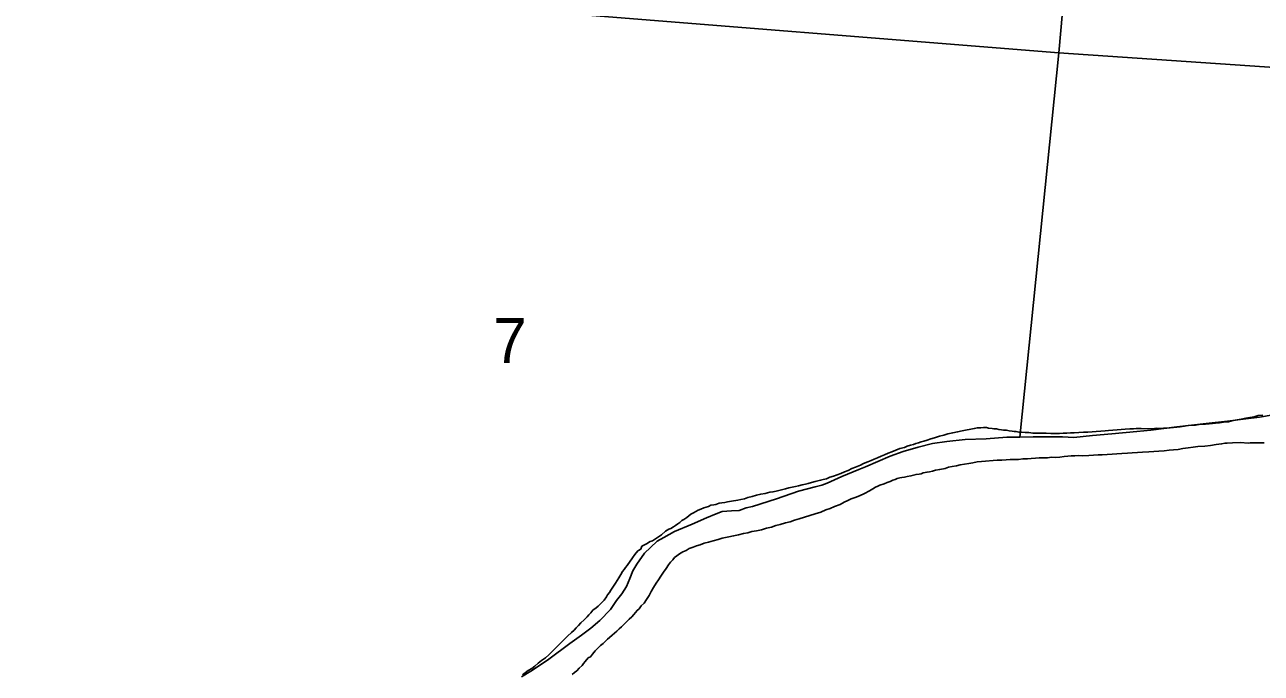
# Model space of a CAD drawing. Extents: x -1.4 to 35.4, y 0 to 22.
# Drawn here: x 20.952 to 22.111, y 16.062 to 16.67 of the extents above; entities that cross this region are included whole.
import ezdxf

# ---------------------------------------------------------------- set-up
doc = ezdxf.new("R2010")
doc.units = 0
for name, color, linetype in [('GM_X_Major_River', 7, 'Continuous'), ('GM_X_Section', 7, 'Continuous'), ('GM_X_Section_Text', 7, 'Continuous')]:
    doc.layers.add(name, color=color, linetype=linetype)

msp = doc.modelspace()

# ---------------------------------------------------------------- linework, layer by layer
at = {"layer": 'GM_X_Major_River'}
for points in [[(22.0755, 16.2976), (22.0804, 16.2979), (22.0846, 16.299), (22.0884, 16.2997), (22.0922, 16.3004), (22.0964, 16.3011), (22.1002, 16.3018), (22.1044, 16.3025), (22.1082, 16.3036), (22.1124, 16.3039)], [(21.7271, 16.254), (21.7306, 16.2554), (21.7352, 16.2573), (21.7382, 16.2587), (21.742, 16.2602), (21.7451, 16.2617), (21.7481, 16.2628), (21.7512, 16.2642), (21.7546, 16.2657), (21.7577, 16.2668), (21.7611, 16.2683), (21.7645, 16.2698), (21.7684, 16.2712), (21.7722, 16.2727), (21.7764, 16.2738), (21.779, 16.2749), (21.7821, 16.276), (21.7848, 16.2767), (21.787, 16.2774), (21.7897, 16.2781), (21.792, 16.2789), (21.7947, 16.2796), (21.7977, 16.2807), (21.8011, 16.2818), (21.8046, 16.2829), (21.8092, 16.2843), (21.8133, 16.2854), (21.8172, 16.2865), (21.8217, 16.2876), (21.8263, 16.2883), (21.8305, 16.2893), (21.8419, 16.2914), (21.8449, 16.2922), (21.848, 16.2921), (21.8506, 16.2925), (21.8533, 16.2924), (21.8552, 16.292), (21.8586, 16.2916), (21.8605, 16.2912), (21.8628, 16.2911), (21.865, 16.2907), (21.8673, 16.2903), (21.8696, 16.2899), (21.8722, 16.2899), (21.8745, 16.2895), (21.8775, 16.289), (21.8794, 16.2886), (21.8813, 16.2886), (21.8836, 16.2882), (21.8863, 16.2882), (21.8897, 16.2877), (21.8931, 16.2877), (21.8969, 16.2872), (21.9011, 16.2872), (21.9052, 16.2871), (21.9094, 16.2871), (21.9136, 16.287), (21.9185, 16.2869), (21.9219, 16.2869), (21.9254, 16.2872), (21.9288, 16.2872), (21.9322, 16.2875), (21.9356, 16.2874), (21.9398, 16.2878), (21.9444, 16.2881), (21.9485, 16.288), (21.9523, 16.2883), (21.9561, 16.2887), (21.9607, 16.289), (21.9645, 16.2893), (21.9679, 16.2896), (21.9717, 16.29), (21.9759, 16.2903), (21.9797, 16.2906), (21.9835, 16.2909), (21.9877, 16.2913), (21.9911, 16.2912), (21.9938, 16.2916), (21.9957, 16.2915), (21.9983, 16.2915), (22.0089, 16.2913), (22.0124, 16.2917), (22.0158, 16.2916), (22.0192, 16.2919), (22.0226, 16.2919), (22.0257, 16.2922), (22.0287, 16.2926), (22.0317, 16.2929), (22.0348, 16.2932), (22.039, 16.2936), (22.0424, 16.2943), (22.0458, 16.2946), (22.0492, 16.2946), (22.0527, 16.2953), (22.0557, 16.2956), (22.0587, 16.2956), (22.0622, 16.2959), (22.0652, 16.2962), (22.0682, 16.2966), (22.0717, 16.2969), (22.0755, 16.2976)], [(22.1136, 16.2781), (22.1109, 16.2781), (22.109, 16.2781), (22.1056, 16.2782), (22.1029, 16.2782), (22.1007, 16.2782), (22.0988, 16.2779), (22.0915, 16.2784), (22.0839, 16.2781), (22.079, 16.2778), (22.0771, 16.2778), (22.0737, 16.2771), (22.0687, 16.2764), (22.0634, 16.2757), (22.0581, 16.275), (22.0516, 16.2748), (22.0471, 16.2741), (22.0425, 16.2734), (22.0376, 16.2727), (22.033, 16.272), (22.0288, 16.2717)], [(22.0288, 16.2717), (22.0246, 16.2713), (22.0201, 16.2707), (22.0148, 16.2703), (22.0102, 16.27), (22.0056, 16.2697), (21.9996, 16.2694), (21.995, 16.2691), (21.9901, 16.2688), (21.9855, 16.2685), (21.9802, 16.2682), (21.9756, 16.2679), (21.9711, 16.2676), (21.9665, 16.2672), (21.9619, 16.2669), (21.9581, 16.267), (21.9536, 16.2667), (21.9494, 16.2663), (21.9437, 16.266), (21.9399, 16.2661), (21.9361, 16.2658), (21.9327, 16.2658), (21.9296, 16.2655), (21.9262, 16.2652), (21.922, 16.2648), (21.9182, 16.2645), (21.9144, 16.2646), (21.9106, 16.2642), (21.9068, 16.2639), (21.9027, 16.264), (21.8993, 16.2636), (21.8954, 16.2633), (21.8917, 16.263), (21.8875, 16.2631), (21.8833, 16.2624), (21.8791, 16.2624), (21.8757, 16.2625), (21.8719, 16.2621), (21.8677, 16.2618), (21.8635, 16.2619), (21.8487, 16.2606), (21.8445, 16.2602), (21.8407, 16.2595), (21.8369, 16.2588), (21.8327, 16.2581), (21.8286, 16.2574), (21.8251, 16.2567), (21.8213, 16.256), (21.8179, 16.2553), (21.8145, 16.2542), (21.8095, 16.2532), (21.8057, 16.2524), (21.8027, 16.2517), (21.8, 16.251), (21.7977, 16.2507), (21.7958, 16.2503), (21.7939, 16.25), (21.792, 16.2492), (21.7901, 16.2489), (21.7874, 16.2485), (21.7848, 16.2478), (21.7825, 16.2471), (21.7791, 16.2467), (21.7764, 16.246), (21.7741, 16.2457), (21.7722, 16.2453), (21.7695, 16.2446), (21.7676, 16.2439), (21.7657, 16.2431), (21.7631, 16.242), (21.7604, 16.2409), (21.7573, 16.2398), (21.7535, 16.2384), (21.7516, 16.2376), (21.7493, 16.2365), (21.7467, 16.2351), (21.7436, 16.2332), (21.739, 16.2306), (21.7344, 16.2284), (21.7302, 16.2269), (21.7264, 16.2255), (21.7234, 16.224), (21.7199, 16.2225), (21.7161, 16.2203), (21.7108, 16.2185), (21.7069, 16.2166), (21.7027, 16.2152), (21.6982, 16.2133), (21.6928, 16.2115), (21.6776, 16.2068), (21.6734, 16.2057), (21.6692, 16.2042), (21.665, 16.2032), (21.66, 16.2017), (21.6559, 16.2006), (21.6517, 16.1992), (21.6471, 16.1981), (21.6425, 16.1966), (21.6376, 16.1956), (21.6334, 16.1949), (21.6296, 16.1938)], [(21.4363, 16.0742), (21.4398, 16.0768), (21.4432, 16.0794), (21.4459, 16.0824), (21.4494, 16.0858), (21.4533, 16.0899), (21.4575, 16.094), (21.4606, 16.097), (21.4644, 16.1004), (21.4667, 16.1026), (21.4686, 16.1049), (21.4709, 16.1071), (21.4732, 16.1094), (21.4763, 16.1124), (21.479, 16.115), (21.4805, 16.1169), (21.4825, 16.1188), (21.4844, 16.1214), (21.4875, 16.1236), (21.4894, 16.1251), (21.4925, 16.1281), (21.4948, 16.1307), (21.4971, 16.1337), (21.4982, 16.1356), (21.4998, 16.1379), (21.5013, 16.1401), (21.5037, 16.1439), (21.5056, 16.1465), (21.5071, 16.1492), (21.5087, 16.1518), (21.5106, 16.1548), (21.5122, 16.1575), (21.5137, 16.1593), (21.5149, 16.1612), (21.5164, 16.1631), (21.5215, 16.1703), (21.5238, 16.1736), (21.5265, 16.177), (21.5292, 16.1785), (21.5303, 16.1812), (21.5345, 16.1834), (21.538, 16.1856), (21.5403, 16.1863), (21.5487, 16.1919), (21.5525, 16.1953), (21.5556, 16.1971), (21.5575, 16.1979), (21.5598, 16.1993), (21.5617, 16.2008), (21.564, 16.2023), (21.5659, 16.2034), (21.5678, 16.2053), (21.5697, 16.2064), (21.5724, 16.2083), (21.5763, 16.2113), (21.5786, 16.2124), (21.5809, 16.2139), (21.5831, 16.215), (21.5854, 16.2161), (21.5885, 16.2172), (21.5904, 16.2179), (21.5927, 16.2186), (21.595, 16.2197), (21.5976, 16.2201), (21.5995, 16.2204), (21.6026, 16.2215), (21.6053, 16.2219), (21.6079, 16.2222), (21.6106, 16.2229), (21.6144, 16.2236), (21.6201, 16.2243), (21.6231, 16.225), (21.6266, 16.2258), (21.6296, 16.2268), (21.6338, 16.2279), (21.6376, 16.229), (21.6418, 16.2301), (21.646, 16.2308), (21.6502, 16.2319), (21.6532, 16.2322), (21.6563, 16.2329), (21.665, 16.2351), (21.6681, 16.2358), (21.6711, 16.2365), (21.6742, 16.2372), (21.6772, 16.2379), (21.6806, 16.2387), (21.6837, 16.2394), (21.6863, 16.2401), (21.6894, 16.2408), (21.6928, 16.2419), (21.6978, 16.243), (21.7004, 16.2437), (21.7035, 16.2444), (21.7065, 16.2459), (21.71, 16.247), (21.7134, 16.2481), (21.7168, 16.2495), (21.7203, 16.251), (21.7237, 16.2521), (21.7271, 16.254)], [(21.6296, 16.1938), (21.6254, 16.1931), (21.6208, 16.192), (21.6163, 16.1909), (21.6117, 16.1899), (21.6056, 16.1888), (21.6018, 16.1877), (21.5972, 16.1863), (21.5926, 16.1852), (21.5888, 16.1841), (21.585, 16.1826), (21.5816, 16.1816), (21.5785, 16.1805), (21.5747, 16.179), (21.5717, 16.1771), (21.5686, 16.176), (21.5655, 16.1742), (21.5632, 16.1723), (21.5609, 16.1708), (21.5594, 16.1686), (21.5571, 16.1663), (21.5552, 16.1637), (21.5532, 16.1603), (21.5505, 16.1569), (21.5482, 16.1532), (21.5459, 16.1498), (21.5436, 16.1468), (21.5412, 16.1426), (21.5389, 16.1388), (21.537, 16.1351), (21.5346, 16.1313), (21.5323, 16.1279), (21.5296, 16.1253), (21.5277, 16.1227), (21.5258, 16.1212), (21.5242, 16.1193), (21.5227, 16.1174), (21.5208, 16.1152), (21.5185, 16.1129), (21.5112, 16.1058), (21.5089, 16.1039), (21.5069, 16.1017), (21.5046, 16.0998), (21.5023, 16.098), (21.5, 16.0957), (21.4981, 16.0942), (21.4962, 16.0923), (21.4939, 16.0901), (21.4916, 16.0882), (21.4897, 16.0864), (21.4866, 16.0834), (21.4839, 16.08), (21.482, 16.0777), (21.48, 16.0766), (21.477, 16.0732), (21.4754, 16.0714), (21.4743, 16.0695), (21.4716, 16.0669), (21.4693, 16.0646), (21.467, 16.0631), (21.465, 16.0612)], [(21.4183, 16.0608), (21.421, 16.0626), (21.4237, 16.0649), (21.4271, 16.0667), (21.4298, 16.069), (21.4329, 16.0716), (21.4363, 16.0742)]]:
    msp.add_lwpolyline(points, dxfattribs=at)
at = {"layer": 'GM_X_Section'}
msp.add_lwpolyline([(21.0375, 17.7298), (22.0102, 17.64), (21.9211, 16.6434), (20.9517, 16.7211)], close=True, dxfattribs=at)
for points in [[(20.9517, 16.7211), (21.9211, 16.6434), (21.8845, 16.2835), (21.8724, 16.2833), (21.853, 16.282), (21.8333, 16.2812), (21.8163, 16.2795), (21.8026, 16.2774), (21.7893, 16.2742), (21.7752, 16.2699), (21.763, 16.2655), (21.7398, 16.2556), (21.7336, 16.2531), (21.7177, 16.2465), (21.704, 16.2402), (21.699, 16.2384), (21.6926, 16.237), (21.677, 16.2327), (21.6564, 16.2258), (21.634, 16.2185), (21.6279, 16.2171), (21.6214, 16.2146), (21.6142, 16.2143), (21.6055, 16.2137), (21.5998, 16.2115), (21.591, 16.2078), (21.5773, 16.2019), (21.5609, 16.195), (21.551, 16.1894), (21.5445, 16.1861), (21.5384, 16.1802), (21.5326, 16.1746), (21.5257, 16.1644), (21.5218, 16.1581), (21.519, 16.1509), (21.5159, 16.1434), (21.5116, 16.1366), (21.5066, 16.1303), (21.5008, 16.122), (21.4908, 16.1116), (21.4824, 16.1045), (21.4736, 16.0978), (21.4628, 16.09), (21.4429, 16.0755), (21.4276, 16.0651), (21.4173, 16.0588)], [(22.1222, 16.3042), (22.1093, 16.3022), (22.0964, 16.3005), (22.0793, 16.2984), (22.0592, 16.2961), (22.0319, 16.2931), (22.0076, 16.29), (21.9944, 16.2887), (21.9709, 16.2864), (21.9527, 16.2851), (21.9352, 16.2831), (21.9246, 16.2836), (21.897, 16.2836), (21.8845, 16.2835), (21.9211, 16.6434), (22.4447, 16.6078)]]:
    msp.add_lwpolyline(points, dxfattribs=at)

# ---------------------------------------------------------------- texts
at = {"layer": 'GM_X_Section_Text'}
msp.add_text('7', height=0.0419, rotation=0, dxfattribs=at).set_placement((21.3911, 16.353))

doc.saveas('drawing.dxf')
